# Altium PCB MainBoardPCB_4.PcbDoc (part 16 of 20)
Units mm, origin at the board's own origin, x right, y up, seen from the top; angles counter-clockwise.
Board outline 333.63 x 349.38 mm, 16 copper layers (L1, L2 (GND), L3 (Sign), L4 (GND), L5 (Sign), L6 (PWR/GND), L7(PWR/GND), L8 (Plane_GND), L9 (PWR/GND), L10 (PWR/GND), L11 (PWR/GND), L12 (Sign), L13 (GND), L14 (Sign), L15 (GND), L16), stack 2.502 mm thick; 2205 components, 1648 nets, 8314 pads, 3172 vias.
Unrouted connection lines stored in the file: 5141.
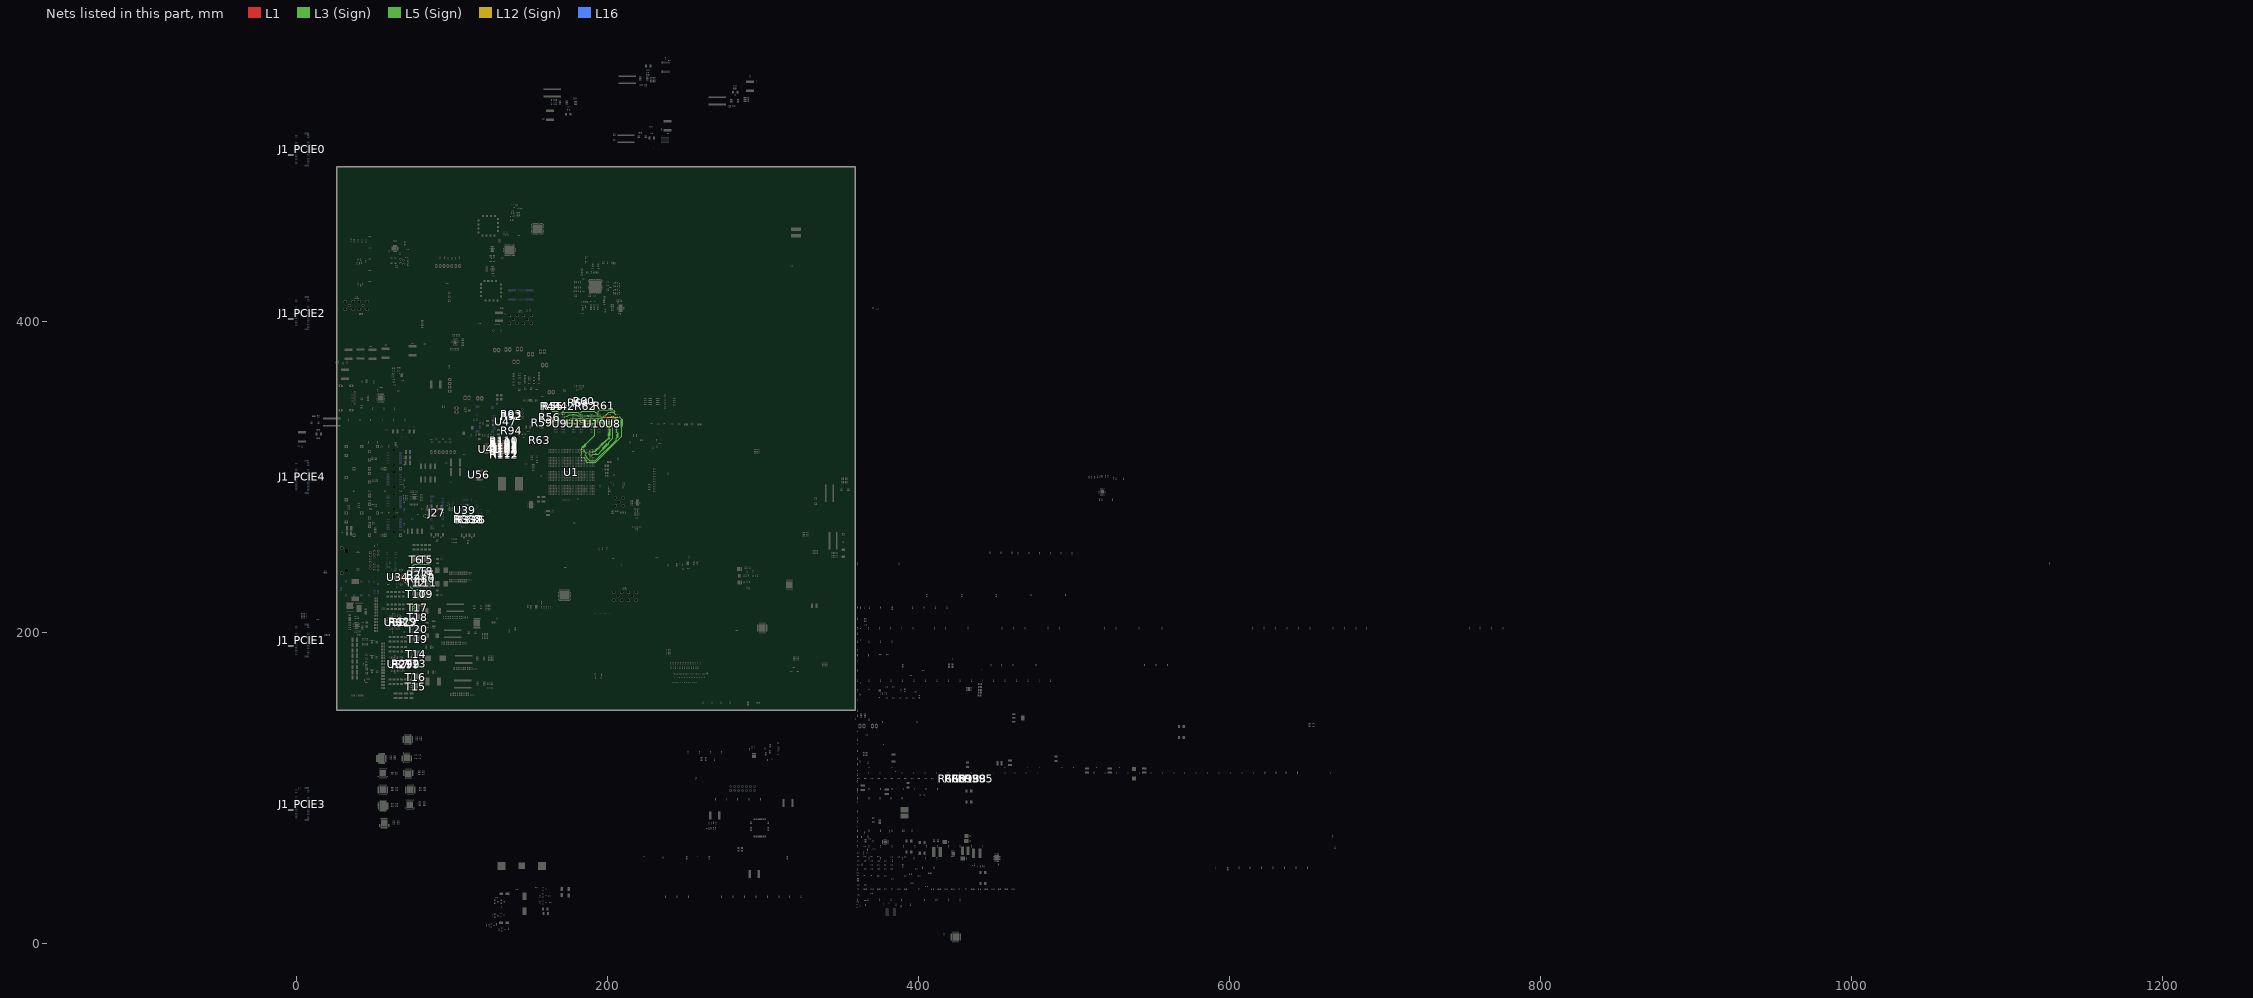
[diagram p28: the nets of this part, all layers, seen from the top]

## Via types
v1: diameter 0.5, hole 0.2, L1 to L16, tented both sides, 1153 vias
v2: diameter 0.5/0.35/0.35/0.35/0.35/0.35/0.35/0.35/0.35/0.35/0.35/0.35/0.35/0.35/0.35/0.5 (per signal layer), hole 0.2, L1 to L16, tented both sides, 548 vias
v3: diameter 0.5, hole 0.2, L1 to L16, 522 vias
v4: diameter 0.5/0.35/0.35/0.35/0.35/0.35/0.35/0.35/0.35/0.35/0.35/0.35/0.35/0.35/0.35/0.5 (per signal layer), hole 0.15, L1 to L16, tented both sides, 266 vias
v5: diameter 0.8, hole 0.4, L1 to L16, tented both sides, 164 vias
v6: diameter 0.35/0/0.35 (per signal layer), hole 0.127, L1 to L3 (Sign), tented both sides, 132 vias
v7: diameter 2.54, hole 1.02, L1 to L16, 125 vias
v8: diameter 1.4, hole 0.5, L1 to L16, tented both sides, 80 vias
v9: diameter 0.35, hole 0.127, L1 to L2 (GND), tented both sides, 36 vias
v10: diameter 0.4, hole 0.2, L1 to L16, 16 vias
v11: diameter 0.25, hole 0.2, L1 to L16, 16 vias
v12: diameter 5, hole 3, L1 to L16, 15 vias
v13: diameter 0.3, hole 0.2, L1 to L16, 15 vias
v14: diameter 0.45, hole 0.15, L1 to L16, 12 vias
v15: diameter 0.5/0.35/0.35/0.35/0.35/0.35/0.35/0.35/0.35/0.35/0.35/0.35/0.35/0.35/0.35/0.45 (per signal layer), hole 0.15, L1 to L16, tented both sides, 10 vias
v16: diameter 0.2/0/0.2 (per signal layer), hole 0.1, L1 to L3 (Sign), tented both sides, 9 vias
v17: diameter 0.4, hole 0.1, L1 to L16, 7 vias
v18: diameter 0.5, hole 0.2, L3 (Sign) to L6 (PWR/GND), tented both sides, 6 vias
v19: diameter 1.65, hole 1.65, L1 to L16, 6 vias
v20: diameter 1.15, hole 1.15, L1 to L16, 6 vias
v21: diameter 0.35/0/0.35 (per signal layer), hole 0.127, L14 (Sign) to L16, tented both sides, 5 vias
v22: diameter 0.2, hole 0.1, L1 to L16, 4 vias
v23: diameter 0.4, hole 0.2, L1 to L16, tented both sides, 2 vias
v24: diameter 0.4, hole 0.15, L1 to L16, 2 vias
v25: diameter 0.508, hole 0.127, L1 to L2 (GND), 2 vias
v26: diameter 0.508, hole 0.127, L2 (GND) to L3 (Sign), 2 vias
v27: diameter 0.5/0.35/0.35/0.35/0.35/0.35/0.35/0.35/0.35/0.35/0.35/0.35/0.35/0.35/0.35/0.5 (per signal layer), hole 0.15, L1 to L16, 2 vias
v28: diameter 0.35, hole 0.127, L3 (Sign) to L6 (PWR/GND), tented both sides, 2 vias
v29: diameter 5.5, hole 3.5, L1 to L16, 1 vias
v30: diameter 0.5/0.35/0.35/0.35/0.35/0.35/0.35/0.35/0.35/0.35/0.35/0.35/0.35/0.35/0.35/0.5 (per signal layer), hole 0.2, L1 to L16, 1 vias
v31: diameter 0.35/0.35/0.35 (per signal layer), hole 0.127, L1 to L3 (Sign), tented both sides, 1 vias
v32: diameter 0.45/0/0.45 (per signal layer), hole 0.15, L1 to L3 (Sign), tented both sides, 1 vias
v33: diameter 0.45/0/0.45 (per signal layer), hole 0.2, L14 (Sign) to L16, tented both sides, 1 vias
v34: diameter 0.35, hole 0.127, L2 (GND) to L3 (Sign), 1 vias
v35: diameter 0.35, hole 0.127, L1 to L2 (GND), 1 vias

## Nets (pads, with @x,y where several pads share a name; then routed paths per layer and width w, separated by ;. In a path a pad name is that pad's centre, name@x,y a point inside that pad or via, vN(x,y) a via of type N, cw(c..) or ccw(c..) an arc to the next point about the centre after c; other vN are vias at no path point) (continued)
DDR4_DQS_ODT0: R44.1 U1.AB30 U8.K3 U9.K3 U10.K3 U11.K3 | length 107.6
  L1 w0.116: v4(170.472,334.857) U9.K3@170.876,335.26 ; v4(181.933,334.857) U11.K3@182.336,335.26 ; U1.AB30@183.397,317.539 v6(183.884,317.052) ; v4(193.393,334.857) U10.K3@193.797,335.26 ; U8.K3@205.257,335.26 v4(205.661,334.857)
  L1 w0.155: v1(163.977,343.555) R44.1@163.977,344.8
  L1 w0.25: v4(188.593,333.264) 188.997,332.86
  L5 (Sign) w0.092: 167.944,341.085 167.944,341.002 168.602,340.344 168.602,336.427 170.172,334.857 v4(170.472,334.857) 170.709,334.857 171.12,335.267 173.139,335.267 173.954,334.453 174.088,334.453 cw(c174.088,334.363) 174.178,334.363 174.178,334.334 ccw(c174.267,334.334) 174.267,334.245 174.536,334.245 ccw(c174.536,334.334) 174.626,334.334 174.626,334.363 cw(c174.715,334.363) 174.715,334.453 176.441,334.453 178.208,334.453 178.601,334.06 180.755,334.06 181.551,334.857 v4(181.933,334.857) 182.566,334.857 182.977,335.267 183.747,335.267 183.972,335.043 183.972,334.696 184.172,334.496 184.934,334.496 185.77,333.66 191.687,333.66 192.884,334.857 193.709,334.857 194.12,335.267 195.118,335.267 195.484,334.901 196.186,334.901 196.783,334.304 196.895,334.304 197.03,334.304 ccw(c197.03,334.393) 197.119,334.393 197.119,334.474 cw(c197.209,334.474) 197.209,334.564 197.477,334.564 cw(c197.477,334.474) 197.567,334.474 197.567,334.304 197.567,333.733 ccw(c197.657,333.733) 197.657,333.644 197.925,333.644 ccw(c197.925,333.733) 198.015,333.733 198.015,334.304 198.015,334.475 cw(c198.104,334.475) 198.104,334.565 198.373,334.565 cw(c198.373,334.475) 198.463,334.475 198.463,334.393 ccw(c198.552,334.393) 198.552,334.304 198.91,334.304 cw(c198.98,334.304) 198.98,334.373 199.289,334.373 cw(c199.289,334.304) 199.358,334.304 199.358,333.855 ccw(c199.448,333.855) 199.448,333.765 199.716,333.765 ccw(c199.716,333.855) 199.806,333.855 199.806,334.214 cw(c199.896,334.214) 199.896,334.304 200.29,334.304 201.429,335.442 205.075,335.442 v4(205.661,334.857)
  L5 (Sign) w0.151: v1(163.977,343.555) 163.977,342.74 164.655,342.062 167.145,342.062 167.944,341.263 167.944,341.085
  L3 (Sign) w0.092: v6(183.884,317.052) 184.243,317.411 184.979,317.411 185.205,317.185 185.205,316.482 186.422,315.264 186.422,314.708 186.421,314.706 186.418,314.706 186.066,314.354 185.884,314.354 185.696,314.166 185.696,313.9 186.28,313.315 186.28,312.749 188.799,310.23 192.379,310.23 205.605,323.456 205.605,324.666 206.306,325.367 206.366,325.428 ccw(c206.296,325.498) 206.366,325.568 206.14,325.794 cw(c206.21,325.865) 206.14,325.935 206.28,326.075 cw(c206.351,326.005) 206.421,326.075 206.647,325.849 ccw(c206.717,325.919) 206.787,325.849 206.858,325.919 206.858,326.275 206.858,326.573 ccw(c206.758,326.573) 206.758,326.672 206.306,326.672 cw(c206.306,326.771) 206.207,326.771 206.207,326.97 cw(c206.306,326.97) 206.306,327.069 206.758,327.069 ccw(c206.758,327.168) 206.858,327.168 206.858,327.466 206.858,327.665 206.858,327.863 206.055,328.665 206.055,334.462 v4(205.661,334.857)
DDR4_DQS_ODT1: U1.AC29
DDR4_PARITY: R42.1 U1.AB26 U8.T3 U9.T3 U10.T3 U11.T3 | length 98
  L1 w0.116: v4(170.472,340.464) U9.T3@170.876,340.06 ; v4(181.933,340.464) U11.T3@182.336,340.06 ; v6(182.909,314.027) U1.AB26@183.397,313.539 ; v4(193.393,340.464) U10.T3@193.797,340.06 ; v15(204.853,340.464) U8.T3@205.257,340.06
  L1 w0.155: v6(172.438,343.555) R42.1@172.438,344.799
  L5 (Sign) w0.092: v4(170.472,340.464) 171.401,341.393 171.535,341.393 ccw(c171.535,341.482) 171.625,341.482 171.625,341.494 cw(c171.714,341.494) 171.714,341.584 171.983,341.584 cw(c171.983,341.494) 172.073,341.494 172.073,341.393 172.073,341.291 ccw(c172.162,341.291) 172.162,341.202 172.431,341.202 ccw(c172.431,341.291) 172.52,341.291 172.52,341.303 cw(c172.61,341.303) 172.61,341.393 173.009,341.393 181.004,341.393 v4(181.933,340.464) 183.734,342.265 188.493,342.265 189.683,342.265 cw(c189.683,342.196) 189.752,342.196 189.752,342.188 ccw(c189.821,342.188) 189.821,342.118 190.029,342.118 ccw(c190.029,342.188) 190.098,342.188 190.098,342.196 cw(c190.168,342.196) 190.168,342.265 190.271,342.265 191.592,342.265 v4(193.393,340.464) 193.568,340.639 193.943,340.639 194.285,340.982 194.285,342.24 194.907,342.862 200.863,342.862 202.534,342.862 cw(c202.534,342.772) 202.623,342.772 202.623,342.659 ccw(c202.713,342.659) 202.713,342.57 202.982,342.57 ccw(c202.982,342.659) 203.071,342.659 203.071,342.862 203.071,343.065 cw(c203.161,343.065) 203.161,343.154 203.429,343.154 cw(c203.429,343.065) 203.519,343.065 203.519,342.862 203.519,342.659 ccw(c203.608,342.659) 203.608,342.57 203.877,342.57 ccw(c203.877,342.659) 203.967,342.659 203.967,342.772 cw(c204.056,342.772) 204.056,342.862 204.191,342.862 204.853,342.199 v15(204.853,340.464)
  L3 (Sign) w0.092: v4(170.472,340.464) 171.013,341.005 171.013,341.085 ; v6(182.909,314.027) 183.49,314.607 183.49,316.403 183.179,316.713 183.179,317.344 183.49,317.654 183.49,318.295 183.84,318.646 183.911,318.716 ccw(c183.84,318.786) 183.911,318.857 183.788,318.979 cw(c183.858,319.049) 183.788,319.119 183.929,319.26 cw(c183.999,319.189) 184.069,319.26 184.261,319.067 184.676,318.653 ccw(c184.746,318.723) 184.816,318.653 184.957,318.793 ccw(c184.886,318.863) 184.957,318.933 184.542,319.348 184.35,319.54 cw(c184.42,319.611) 184.35,319.681 184.49,319.821 cw(c184.56,319.751) 184.63,319.821 184.823,319.629 185.201,319.251 ccw(c185.271,319.321) 185.341,319.251 185.481,319.391 ccw(c185.411,319.461) 185.481,319.531 185.104,319.909 184.911,320.102 cw(c184.981,320.172) 184.911,320.242 185.051,320.383 cw(c185.122,320.312) 185.192,320.383 185.384,320.19 185.76,319.814 ccw(c185.83,319.884) 185.9,319.814 186.041,319.955 ccw(c185.971,320.025) 186.041,320.095 185.665,320.471 185.472,320.663 cw(c185.543,320.733) 185.472,320.804 185.613,320.944 cw(c185.683,320.874) 185.753,320.944 185.876,320.822 ccw(c185.946,320.892) 186.016,320.822 186.715,321.521 191.937,326.742 191.937,334.292 192.646,335.002 192.646,336.014 193.206,336.574 196.129,336.574 201.059,341.503 203.814,341.503 v15(204.853,340.464)
  L3 (Sign) w0.151: 171.013,341.085 171.013,341.464 172.428,342.879 172.428,343.545 v6(172.438,343.555)
DDR4_RAM_RST_N: R60.1 U1.AB25 U8.P1 U9.P1 U10.P1 U11.P1 | length 99.4
  L1 w0.116: U9.P1@172.476,338.46 v6(172.879,338.864) ; U1.AB25@183.397,312.539 v6(183.884,313.027) ; U11.P1@183.936,338.46 v6(184.34,338.864) ; U10.P1@195.397,338.46 v4(195.8,338.864) ; U8.P1@206.857,338.46 v4(207.261,338.864)
  L12 (Sign) w0.092: v4(195.8,338.864) 196.374,338.29 201.123,338.29 201.218,338.385 202.425,338.385 202.56,338.385 ccw(c202.56,338.475) 202.649,338.475 202.649,338.652 cw(c202.739,338.652) 202.739,338.742 203.007,338.742 cw(c203.007,338.652) 203.097,338.652 203.097,338.385 203.097,338.118 ccw(c203.187,338.118) 203.187,338.028 203.455,338.028 ccw(c203.455,338.118) 203.545,338.118 203.545,338.385 203.545,338.652 cw(c203.634,338.652) 203.634,338.742 203.903,338.742 cw(c203.903,338.652) 203.993,338.652 203.993,338.475 ccw(c204.082,338.475) 204.082,338.385 204.483,338.385 206.782,338.385 v4(207.261,338.864)
  L3 (Sign) w0.092: v6(172.879,338.864) 174.191,338.864 175.387,340.06 175.672,340.06 cw(c175.672,339.951) 175.782,339.951 175.782,339.92 ccw(c175.892,339.92) 175.892,339.81 176.222,339.81 ccw(c176.222,339.92) 176.332,339.92 176.332,339.951 cw(c176.441,339.951) 176.441,340.06 176.606,340.06 179.992,340.06 180.792,339.26 183.943,339.26 v6(184.34,338.864) 184.736,339.26 185.89,339.26 187.297,339.26 ccw(c187.297,339.35) 187.387,339.35 187.387,339.625 cw(c187.476,339.625) 187.476,339.715 187.745,339.715 cw(c187.745,339.625) 187.834,339.625 187.834,339.26 187.834,339.02 ccw(c187.924,339.02) 187.924,338.93 188.193,338.93 ccw(c188.193,339.02) 188.282,339.02 188.282,339.171 cw(c188.372,339.171) 188.372,339.26 188.506,339.26 195.404,339.26 v4(195.8,338.864) ; v6(183.884,313.027) 184.305,313.027 184.7,312.632 185.055,312.632 185.382,312.306 185.382,311.656 186.28,310.757 186.28,309.749 186.606,309.423 187.731,309.423 192.65,309.423 192.689,309.462 192.697,309.462 209.194,325.959 209.194,331.495 209.194,332.123 ccw(c209.057,332.123) 209.057,332.26 208.801,332.26 cw(c208.801,332.398) 208.663,332.398 208.663,332.672 cw(c208.801,332.672) 208.801,332.81 209.194,332.81 209.71,332.81 ccw(c209.71,332.947) 209.847,332.947 209.847,333.222 ccw(c209.71,333.222) 209.71,333.359 209.194,333.359 208.801,333.359 cw(c208.801,333.496) 208.663,333.496 208.663,333.771 cw(c208.801,333.771) 208.801,333.908 209.194,333.908 209.71,333.908 ccw(c209.71,334.046) 209.847,334.046 209.847,334.32 ccw(c209.71,334.32) 209.71,334.458 209.194,334.458 208.801,334.458 cw(c208.801,334.595) 208.663,334.595 208.663,334.87 cw(c208.801,334.87) 208.801,335.007 209.194,335.007 209.71,335.007 ccw(c209.71,335.145) 209.847,335.145 209.847,335.419 ccw(c209.71,335.419) 209.71,335.557 209.194,335.557 208.801,335.557 cw(c208.801,335.694) 208.663,335.694 208.663,335.969 cw(c208.801,335.969) 208.801,336.106 209.194,336.106 209.71,336.106 ccw(c209.71,336.243) 209.847,336.243 209.847,336.518 ccw(c209.71,336.518) 209.71,336.655 209.332,336.655 cw(c209.332,336.793) 209.194,336.793 209.194,336.93 v4(207.261,338.864)
DDR4_RAS: R59.1 U1.AH27 U8.L5 U9.L5 U10.L5 U11.L5 | length 99.3
  L1 w0.116: U9.L5@166.876,336.06 167.272,336.457 v4(167.275,336.457) ; U11.L5@178.336,336.06 178.733,336.457 v4(178.735,336.457) ; U1.AH27@189.397,314.539 v6(189.884,315.027) ; U10.L5@189.797,336.06 190.193,336.457 v4(190.195,336.457) ; U8.L5@201.257,336.06 201.653,336.457 v3(201.656,336.457)
  L1 w0.155: R59.1@158.737,334.7 v1(159.982,334.7)
  L12 (Sign) w0.092: 165.251,335.813 166.114,335.813 166.758,336.457 v4(167.275,336.457) 167.537,336.457 167.858,336.778 168.277,336.778 168.566,336.488 168.79,336.488 169.149,336.488 cw(c169.149,336.398) 169.238,336.398 169.238,336.342 ccw(c169.328,336.342) 169.328,336.252 169.596,336.252 ccw(c169.596,336.342) 169.686,336.342 169.686,336.398 cw(c169.775,336.398) 169.775,336.488 170.044,336.488 cw(c170.044,336.398) 170.134,336.398 170.134,336.342 ccw(c170.223,336.342) 170.223,336.252 170.492,336.252 ccw(c170.492,336.342) 170.582,336.342 170.582,336.398 cw(c170.671,336.398) 170.671,336.488 170.715,336.488 172.923,336.488 173.147,336.488 173.505,336.488 cw(c173.505,336.398) 173.595,336.398 173.595,336.3 ccw(c173.684,336.3) 173.684,336.211 173.953,336.211 ccw(c173.953,336.3) 174.043,336.3 174.043,336.398 cw(c174.132,336.398) 174.132,336.488 175.628,336.488 175.659,336.457 v4(178.735,336.457) 178.977,336.457 179.349,336.829 180.162,336.829 180.705,336.287 184.769,336.287 184.996,336.06 185.807,336.06 185.91,336.06 ccw(c185.91,336.13) 185.98,336.13 185.98,336.293 cw(c186.049,336.293) 186.049,336.362 186.257,336.362 cw(c186.257,336.293) 186.326,336.293 186.326,336.06 186.326,335.828 ccw(c186.395,335.828) 186.395,335.758 186.603,335.758 ccw(c186.603,335.828) 186.672,335.828 186.672,335.991 cw(c186.741,335.991) 186.741,336.06 186.868,336.06 189.282,336.06 189.679,336.457 v4(190.195,336.457) 190.458,336.457 190.779,336.778 191.197,336.778 191.487,336.488 192.022,335.953 197.764,335.953 198.156,335.953 ccw(c198.156,336.043) 198.245,336.043 198.245,336.152 cw(c198.335,336.152) 198.335,336.241 198.603,336.241 cw(c198.603,336.152) 198.693,336.152 198.693,335.953 198.693,335.754 ccw(c198.782,335.754) 198.782,335.665 199.051,335.665 ccw(c199.051,335.754) 199.141,335.754 199.141,335.864 cw(c199.23,335.864) 199.23,335.953 199.365,335.953 199.502,335.953 ccw(c199.502,336.043) 199.592,336.043 199.592,336.152 cw(c199.681,336.152) 199.681,336.241 199.95,336.241 cw(c199.95,336.152) 200.04,336.152 200.04,335.953 200.04,335.864 ccw(c200.129,335.864) 200.129,335.774 200.398,335.774 ccw(c200.398,335.864) 200.487,335.864 cw(c200.577,335.864) 200.577,335.953 200.711,335.953 201.215,336.457 v3(201.656,336.457)
  L12 (Sign) w0.151: v1(159.982,334.7) 163.09,334.7 164.203,335.813 165.251,335.813
  L3 (Sign) w0.092: v6(189.884,315.027) 190.232,315.374 190.232,316.074 190.672,316.514 190.938,316.514 192.232,316.514 192.381,316.663 192.469,316.751 ccw(c192.381,316.839) 192.469,316.928 192.438,316.959 cw(c192.526,317.047) 192.438,317.135 192.614,317.311 cw(c192.702,317.223) 192.79,317.311 192.91,317.192 192.931,317.17 ccw(c193.019,317.259) 193.107,317.17 193.284,317.347 ccw(c193.196,317.435) 193.284,317.523 193.262,317.544 193.143,317.664 cw(c193.231,317.752) 193.143,317.84 193.319,318.017 cw(c193.407,317.928) 193.495,318.017 193.615,317.897 193.639,317.873 ccw(c193.727,317.961) 193.815,317.873 193.992,318.049 ccw(c193.903,318.137) 193.992,318.225 193.967,318.25 193.848,318.369 cw(c193.936,318.457) 193.848,318.545 194.024,318.722 cw(c194.112,318.634) 194.2,318.722 194.32,318.602 194.473,318.449 ccw(c194.562,318.537) 194.65,318.449 194.826,318.625 ccw(c194.738,318.713) 194.826,318.801 194.673,318.955 194.553,319.074 cw(c194.641,319.162) 194.553,319.251 194.729,319.427 cw(c194.817,319.339) 194.906,319.427 195.025,319.307 195.098,319.235 ccw(c195.186,319.323) 195.274,319.235 195.45,319.411 ccw(c195.362,319.499) 195.45,319.587 195.378,319.66 195.258,319.779 cw(c195.346,319.868) 195.258,319.956 195.434,320.132 cw(c195.523,320.044) 195.611,320.132 195.73,320.012 195.826,319.917 ccw(c195.914,320.005) 196.002,319.917 196.179,320.093 ccw(c196.09,320.181) 196.179,320.269 196.083,320.365 195.963,320.485 cw(c196.051,320.573) 195.963,320.661 196.14,320.837 cw(c196.228,320.749) 196.316,320.837 196.435,320.718 196.589,320.564 ccw(c196.677,320.652) 196.765,320.564 196.941,320.74 ccw(c196.853,320.829) 196.941,320.917 196.788,321.07 196.668,321.19 cw(c196.757,321.278) 196.668,321.366 196.845,321.542 cw(c196.933,321.454) 197.021,321.542 197.14,321.423 197.232,321.331 ccw(c197.32,321.419) 197.408,321.331 197.585,321.508 ccw(c197.496,321.596) 197.585,321.684 197.493,321.775 197.373,321.895 cw(c197.462,321.983) 197.373,322.071 197.55,322.247 cw(c197.638,322.159) 197.726,322.247 197.846,322.128 197.961,322.013 ccw(c198.049,322.101) 198.137,322.013 198.313,322.189 ccw(c198.225,322.277) 198.313,322.365 198.198,322.48 198.079,322.6 cw(c198.167,322.688) 198.079,322.776 198.255,322.953 cw(c198.343,322.864) 198.431,322.953 198.551,322.833 198.702,322.682 ccw(c198.79,322.77) 198.878,322.682 199.054,322.858 ccw(c198.966,322.946) 199.054,323.035 198.903,323.186 198.784,323.305 cw(c198.872,323.393) 198.784,323.481 198.96,323.658 cw(c199.048,323.569) 199.136,323.658 199.256,323.538 199.341,323.453 ccw(c199.43,323.541) 199.518,323.453 199.694,323.629 ccw(c199.606,323.717) 199.694,323.805 199.697,323.802 cw(c199.785,323.891) 199.697,323.979 199.873,324.155 cw(c199.961,324.067) 200.049,324.155 200.201,324.003 ccw(c200.289,324.091) 200.377,324.003 200.554,324.179 ccw(c200.466,324.267) 200.554,324.356 200.402,324.508 cw(c200.49,324.596) 200.402,324.684 200.578,324.86 cw(c200.666,324.772) 200.754,324.86 201.149,324.465 ccw(c201.237,324.554) 201.325,324.465 201.502,324.642 ccw(c201.413,324.73) 201.502,324.818 201.107,325.213 cw(c201.195,325.301) 201.107,325.389 201.224,325.507 201.224,325.653 201.224,326.255 ccw(c201.1,326.255) 201.1,326.38 200.859,326.38 cw(c200.859,326.505) 200.734,326.505 200.734,326.754 cw(c200.859,326.754) 200.859,326.879 201.224,326.879 201.708,326.879 ccw(c201.708,327.003) 201.833,327.003 201.833,327.253 ccw(c201.708,327.253) 201.708,327.377 201.224,327.377 200.859,327.377 cw(c200.859,327.502) 200.734,327.502 200.734,327.751 cw(c200.859,327.751) 200.859,327.876 201.224,327.876 201.708,327.876 ccw(c201.708,328) 201.833,328 201.833,328.25 ccw(c201.708,328.25) 201.708,328.374 201.349,328.374 cw(c201.349,328.499) 201.224,328.499 201.224,328.748 cw(c201.349,328.748) 201.349,328.873 201.708,328.873 ccw(c201.708,328.998) 201.833,328.998 201.833,329.247 ccw(c201.708,329.247) 201.708,329.372 201.224,329.372 cw(c201.224,329.478) 201.118,329.478 201.118,329.764 cw(c201.224,329.764) 201.224,329.87 201.708,329.87 ccw(c201.708,329.995) 201.833,329.995 201.833,330.244 ccw(c201.708,330.244) 201.708,330.369 201.224,330.369 201.133,330.369 cw(c201.133,330.493) 201.009,330.493 201.009,330.743 cw(c201.133,330.743) 201.133,330.867 201.224,330.867 ccw(c201.224,330.931) 201.288,330.931 201.288,331.303 ccw(c201.224,331.303) 201.224,331.366 201.223,331.366 cw(c201.223,331.491) 201.098,331.491 201.098,331.74 cw(c201.223,331.74) 201.223,331.865 201.224,331.865 ccw(c201.224,331.969) 201.329,331.969 201.329,332.259 ccw(c201.224,332.259) 201.224,332.363 cw(c201.224,332.484) 201.103,332.484 201.103,332.741 cw(c201.224,332.741) 201.224,332.862 201.708,332.862 ccw(c201.708,332.986) 201.833,332.986 201.833,333.236 ccw(c201.708,333.236) 201.708,333.36 201.224,333.36 cw(c201.224,333.485) 201.1,333.485 201.1,333.734 cw(c201.224,333.734) 201.224,333.859 201.708,333.859 ccw(c201.708,333.984) 201.833,333.984 201.833,334.233 ccw(c201.708,334.233) 201.708,334.358 201.349,334.358 cw(c201.349,334.482) 201.224,334.482 201.224,334.607 201.224,335.03 201.371,335.177 201.371,335.877 201.656,336.162 v3(201.656,336.457)
  other v19: 2.275,99.582
DDR4_TEN: R56.1 U8.N6 U9.N6 U10.N6 U11.N6 | length 42.1
  L1 w0.112: 165.251,338.056 v6(165.665,338.056)
  L1 w0.116: v6(165.665,338.056) U9.N6@166.068,337.653 ; v6(177.125,338.056) U11.N6@177.529,337.653 ; v6(188.586,338.056) U10.N6@188.989,337.653 ; v6(197.878,339.319) 199.536,337.66 U8.N6@200.457,337.66
  L1 w0.155: R56.1@163.36,338.184 164.159,338.184 164.287,338.056 165.251,338.056
  L3 (Sign) w0.092: v6(165.665,338.056) 166.061,337.66 168.338,337.66 169.439,336.56 175.628,336.56 176.729,337.66
  L3 (Sign) w0.116: 176.729,337.66 v6(177.125,338.056) 177.521,337.66 183.136,337.66 183.143,337.668 188.197,337.668 v6(188.586,338.056) 188.982,337.66 190.855,337.66 190.869,337.674 191.154,337.674 191.313,337.833 192.222,337.833 192.387,337.668 196.227,337.668 v6(197.878,339.319)
DDR4_WE: R55.1 U1.AG29 U8.L2 U9.L2 U10.L2 U11.L2 | length 108.5
  L1 w0.116: U9.L2@171.676,336.06 v4(172.079,335.657) ; U11.L2@183.136,336.06 v4(183.54,335.657) ; U1.AG29@188.397,316.539 188.811,316.125 v6(188.811,316.088) ; U10.L2@194.597,336.06 v4(195,335.657) ; v4(205.653,336.464) U8.L2@206.057,336.06
  L1 w0.155: v1(165.186,343.555) R55.1@165.186,344.8
  L5 (Sign) w0.092: 168.291,341.085 168.291,341.007 168.793,340.505 168.793,336.675 170.132,335.336 170.605,335.336 170.62,335.351 170.791,335.351 171.097,335.657 171.317,335.657 v4(172.079,335.657) 172.129,335.706 173.291,335.706 174.157,334.84 174.291,334.84 ccw(c174.291,334.93) 174.38,334.93 174.38,334.97 cw(c174.47,334.97) 174.47,335.06 174.739,335.06 cw(c174.739,334.97) 174.828,334.97 174.828,334.93 ccw(c174.918,334.93) 174.918,334.84 176.289,334.84 178.225,334.84 178.587,334.478 180.897,334.478 181.669,335.25 182.326,335.25 182.733,335.657 ; v4(205.653,336.464) 205.316,336.464 204.486,335.634 204.352,335.634 cw(c204.352,335.724) 204.262,335.724 204.262,335.829 ccw(c204.173,335.829) 204.173,335.919 203.904,335.919 ccw(c203.904,335.829) 203.814,335.829 203.814,335.724 cw(c203.725,335.724) 203.725,335.634 203.456,335.634 cw(c203.456,335.724) 203.367,335.724 203.367,335.75 ccw(c203.277,335.75) 203.277,335.839 203.008,335.839 ccw(c203.008,335.75) 202.919,335.75 202.919,335.724 cw(c202.829,335.724) 202.829,335.634 202.552,335.634 201.349,335.634 200.925,335.21 200.79,335.21 ccw(c200.79,335.12) 200.701,335.12 200.701,335.023 cw(c200.611,335.023) 200.611,334.933 200.342,334.933 cw(c200.342,335.023) 200.253,335.023 200.253,335.21 200.253,335.257 ccw(c200.163,335.257) 200.163,335.347 199.895,335.347 ccw(c199.895,335.257) 199.805,335.257 199.805,335.21 199.805,334.893 cw(c199.715,334.893) 199.715,334.803 199.447,334.803 cw(c199.447,334.893) 199.357,334.893 199.357,335.21 199.357,335.257 ccw(c199.268,335.257) 199.268,335.347 198.999,335.347 ccw(c198.999,335.257) 198.909,335.257 cw(c198.862,335.257) 198.862,335.21 198.509,335.21 cw(c198.509,335.257) 198.462,335.257 ccw(c198.372,335.257) 198.372,335.347 198.103,335.347 ccw(c198.103,335.257) 198.014,335.257 198.014,335.209 198.014,334.893 cw(c197.924,334.893) 197.924,334.803 197.656,334.803 cw(c197.656,334.893) 197.566,334.893 197.566,335.209 197.566,335.526 ccw(c197.476,335.526) 197.476,335.616 197.208,335.616 ccw(c197.208,335.526) 197.118,335.526 197.118,335.209 197.118,334.893 cw(c197.029,334.893) 197.029,334.803 196.76,334.803 cw(c196.76,334.893) 196.67,334.893 196.67,335.209 196.67,335.526 ccw(c196.581,335.526) 196.581,335.616 196.312,335.616 ccw(c196.312,335.526) 196.223,335.526 196.223,335.299 cw(c196.133,335.299) 196.133,335.209 195.783,335.209 195.721,335.209 195.274,335.657 v4(195,335.657) 194.193,335.657 193.797,335.26 192.558,335.26 191.777,334.48 188.561,334.48 188.457,334.48 ccw(c188.457,334.411) 188.387,334.411 cw(c188.318,334.411) 188.318,334.341 188.111,334.341 cw(c188.111,334.411) 188.041,334.411 188.041,334.48 188.041,334.707 ccw(c187.972,334.707) 187.972,334.776 187.764,334.776 ccw(c187.764,334.707) 187.695,334.707 187.695,334.549 cw(c187.626,334.549) 187.626,334.48 186.969,334.48 185.344,334.48 184.556,335.267 184.187,335.267 183.798,335.657 v4(183.54,335.657) ; 182.733,335.657 v4(183.54,335.657) ; 182.733,335.657 v4(183.54,335.657)
  L5 (Sign) w0.151: v1(165.186,343.555) 165.186,342.893 165.535,342.544 167.348,342.544 168.291,341.601 168.291,341.085
  L3 (Sign) w0.092: v6(188.811,316.088) 188.92,316.088 188.563,315.731 188.563,315.57 188.335,315.341 188.335,314.327 188.397,314.264 188.397,314.06 188.826,313.631 190.119,313.631 190.33,313.842 190.33,314.212 190.592,314.473 191.534,314.473 191.651,314.59 191.872,314.59 191.971,314.59 ccw(c191.971,314.689) 192.07,314.689 cw(c192.169,314.689) 192.169,314.788 192.368,314.788 cw(c192.368,314.689) 192.467,314.689 192.467,314.59 ccw(c192.566,314.59) 192.566,314.491 192.765,314.491 ccw(c192.765,314.59) 192.864,314.59 192.864,314.697 cw(c192.963,314.697) 192.963,314.796 193.162,314.796 cw(c193.162,314.697) 193.261,314.697 193.261,314.689 ccw(c193.36,314.689) 193.36,314.59 193.789,314.59 194.01,314.59 ; 194.009,314.591 196.884,317.466 196.995,317.576 cw(c197.065,317.506) 197.135,317.576 197.133,317.579 ; 197.132,317.579 ccw(c197.203,317.649) 197.273,317.579 197.413,317.719 ccw(c197.343,317.79) 197.413,317.86 197.345,317.927 196.991,318.281 cw(c197.062,318.352) 196.991,318.422 197.132,318.562 cw(c197.202,318.492) 197.272,318.562 197.626,318.208 197.694,318.14 ccw(c197.764,318.211) 197.834,318.14 197.975,318.281 ccw(c197.904,318.351) 197.975,318.421 197.907,318.489 197.553,318.843 cw(c197.623,318.913) 197.553,318.983 197.693,319.124 cw(c197.763,319.053) 197.834,319.124 198.188,318.77 198.255,318.702 ccw(c198.325,318.772) 198.396,318.702 198.536,318.842 ccw(c198.466,318.912) 198.536,318.983 198.468,319.05 198.114,319.404 cw(c198.184,319.475) 198.114,319.545 198.255,319.685 cw(c198.325,319.615) 198.395,319.685 198.749,319.331 198.817,319.263 ccw(c198.887,319.333) 198.957,319.263 199.097,319.404 ccw(c199.027,319.474) 199.097,319.544 199.03,319.612 198.676,319.966 cw(c198.746,320.036) 198.676,320.106 198.816,320.247 cw(c198.886,320.176) 198.956,320.247 199.311,319.892 199.376,319.827 ccw(c199.446,319.897) 199.516,319.827 199.656,319.968 ccw(c199.586,320.038) 199.656,320.108 199.591,320.173 199.237,320.527 cw(c199.307,320.597) 199.237,320.668 199.377,320.808 cw(c199.448,320.738) 199.518,320.808 199.872,320.454 199.937,320.389 ccw(c200.007,320.459) 200.078,320.389 200.218,320.529 ccw(c200.148,320.599) 200.218,320.669 200.153,320.735 199.799,321.089 cw(c199.869,321.159) 199.799,321.229 199.939,321.369 cw(c200.009,321.299) 200.079,321.369 200.433,321.015 200.504,320.945 ccw(c200.574,321.015) 200.644,320.945 200.784,321.085 ccw(c200.714,321.156) 200.784,321.226 cw(c200.855,321.296) 200.784,321.366 200.855,321.436 200.855,322.107 203.626,324.879 203.626,335.895 203.898,336.168 203.898,336.931 203.91,336.942 203.91,336.947 204.419,337.456 204.423,337.456 204.635,337.668 205.034,337.668 205.263,337.439 205.263,336.855 v4(205.653,336.464)
DDR4_ZQ: U1.AB23
DDR4_ZQ_1: R61.1 U8.F6 | length 2.2
  L1 w0.254: v1(198.343,331.916) 198.475,332.048 200.445,332.048 U8.F6@200.457,332.06
DDR4_ZQ_2: R62.1 U10.F6 | length 0.6
  L1 w0.25: v4(188.593,332.464) U10.F6@188.997,332.06
DDR4_ZQ_3: R63.1 U9.F6
DDR4_ZQ_4: R64.1 U11.F6
DEVSLP: J27.38
DEVSLP_PCIE0: J1_PCIE0.40 R395.1 U1.AE5
  other v2: 186.397,292.539
DEVSLP_PCIE1: J1_PCIE1.40 R398.1 U1.AD4
  other v2: 185.397,291.539
DEVSLP_PCIE2: J1_PCIE2.40 R618.1 U1.AE4
  other v2: 186.397,291.539
DEVSLP_PCIE3: J1_PCIE3.40 R659.1 U1.AB4
  other v2: 183.397,291.539
DEVSLP_PCIE4: J1_PCIE4.40 R660.1 U1.AC4
  other v2: 184.397,291.539
DH1: T5.4 T6.4 U34.23 | length 21.5
  L1 w0.254: U34.23@67.322,236.639 67.949,236.639 69.436,238.125 v6(70.117,238.125) ; T5.4@85.882,243.723 v6(85.882,243.755)
  L3 (Sign) w0.254: v6(70.117,238.125) 75.714,243.723 v6(78.882,243.723) 78.914,243.755 v6(85.882,243.755)
DH1_1: T13.4 U37.23 | length 1.1
  L1 w0.5: T13.4@80.042,181.813 v1(81.129,181.813)
DH1_2: T17.4 U38.23 | length 13.5
  L1 w0.254: U38.23@65.953,207.714 67.479,207.714 v6(67.796,208.031) ; v6(80.18,217.889) T17.4@80.998,217.889
  L3 (Sign) w0.254: v6(67.796,208.031) 67.796,210.036 ; 74.923,213.696 74.923,216.666 75.567,217.31 79.083,217.31 79.662,217.889 v6(80.18,217.889)
DH2: T9.4 T10.4 U34.18 | length 17.5
  L1 w0.254: U34.18@67.322,234.139 67.324,234.137 68.428,234.137 v6(69.863,232.702) ; v6(82.067,227.505) T9.4@82.072,227.501
  L3 (Sign) w0.254: v6(69.863,232.702) 75.064,227.501 v6(75.078,227.501) 75.082,227.505 v6(82.067,227.505)
DH2_1: T15.4 U37.18 | length 1.1
  L1 w0.5: T15.4@79.789,167.011 v1(80.876,167.011)
DH2_2: T19.4 U38.18 | length 1.9
  L1 w0.254: U38.18@65.953,205.214 67.536,205.214 67.744,205.006
DIR_CMD: R92.2 U47.A2 | length 4.9
  L16 w0.098: U47.A2@135.129,336.204 135.127,337.538 136.651,339.062 R92.2@138.087,339.062
DIR_DAT0_H: R93.2 U47.A3 | length 5.9
  L16 w0.098: U47.A3@134.727,336.204 134.727,337.729 137.102,340.103 R93.2@138.087,340.103
DIR_DAT1_H: R94.2 U47.E3
DL1: R275.2 T7.4 T8.4 U34.21 | length 19.6
  L1 w0.254: U34.21@67.322,235.639 70.805,235.639 v6(71.387,236.22) ; v6(85.869,236.489) T8.4@85.882,236.489
  L3 (Sign) w0.254: v6(71.387,236.22) 71.655,236.489 v6(78.867,236.489) 79.613,236.489 v6(80.488,237.364) 81.363,236.489 v6(85.869,236.489)
DL1_1: R292.2 T14.4 U37.21 | length 3.6
  L1 w0.254: U37.21@67.675,179.817 68.726,179.817 68.825,179.915 R292.2@70.161,179.915
  L1 w0.5: v1(73.127,184.15) T14.4@74.214,184.15
DL1_2: R629.2 T18.4 U38.21 | length 9.9
  L1 w0.254: U38.21@65.953,206.714 66.916,206.714 67.166,206.964 R629.2@68.206,206.964 ; v6(73.85,207.802) 73.855,207.797 T18.4@75.173,207.797
  L3 (Sign) w0.254: v6(67.43,206.951) 69.233,208.755 ; 71.23,205.181 v6(73.85,207.802)
DL2: R280.2 T11.4 T12.4 U34.20 | length 15.8
  L1 w0.254: U34.20@67.322,235.139 69.941,235.139 v6(70.129,234.95)
  L3 (Sign) w0.254: v6(70.129,234.95) 70.316,234.764 v6(75.072,234.764) v6(82.072,234.764) ; v6(80.488,233.889) 80.488,234.764
DL2_1: R299.2 T16.4 U37.20 | length 3.7
  L1 w0.254: U37.20@67.675,179.317 69.396,179.317 69.646,179.067 R299.2@70.211,179.067
  L1 w0.5: v1(72.923,169.38) T16.4@74.01,169.38
DL2_2: R317.2 T20.4 U38.20 | length 2.3
  L1 w0.254: U38.20@65.953,206.214 66.991,206.214 67.166,206.039 68.212,206.039 R317.2@68.206,206.039
DS_TCK: U39.20 U56.12
DS_TDI: R336.2 U39.23 U56.14
DS_TDO: R337.2 U39.21 U56.11
DS_TMS: R338.2 U39.22 U56.13
eMMC_clk: R112.2 U41.M6 | length 13.8
  L1 w0.098: v6(131.416,314.211) 133.103,314.211 R112.2@133.116,314.223
  L3 (Sign) w0.098: v16(121.938,318.591) 122.886,319.54 125.022,319.54 130.352,314.211 v6(131.416,314.211)
eMMC_cmd: R111.2 U41.M5 | length 13.3
  L1 w0.098: v6(131.407,315.214) R111.2@133.116,315.214
  L3 (Sign) w0.098: v16(121.938,319.091) 122.157,319.091 122.804,319.738 125.104,319.738 129.629,315.214 v6(131.407,315.214)
eMMC_data0: R105.2 U41.A3 | length 6.2
  L1 w0.098: v6(131.407,321.335) R105.2@133.116,321.335
  L3 (Sign) w0.098: v16(127.438,320.091) 128.682,321.335 v6(131.407,321.335)
eMMC_data1: R107.2 U41.A4 | length 5.8
  L1 w0.098: U41.A4@127.438,319.591 130.833,319.591 131.121,319.303 R107.2@133.116,319.303
eMMC_data2: R108.2 U41.A5 | length 6.4
  L1 w0.098: U41.A5@127.438,319.091 128.558,319.091 130.378,317.271 R108.2@133.116,317.271
eMMC_data3: R110.2 U41.B2 | length 7.3
  L1 w0.098: v32(131.416,323.367) R110.2@133.116,323.367
  L3 (Sign) w0.098: v16(126.938,320.591) 129.714,323.367 v32(131.416,323.367)
eMMC_data4: R101.2 U41.B3 | length 7.1
  L1 w0.098: v16(126.929,320.091) U41.B3@126.938,320.091 ; v6(131.407,322.351) R101.2@133.116,322.351
  L3 (Sign) w0.098: v16(126.929,320.091) 128.897,322.059 128.905,322.059 129.197,322.351 v6(131.407,322.351)
eMMC_data5: R102.2 U41.B4 | length 6.6
  L1 w0.098: v6(131.407,320.319) 131.466,320.319 131.665,320.518 132.917,320.518 R102.2@133.116,320.319
  L3 (Sign) w0.098: v16(126.938,319.591) 127.478,319.591 128.207,320.319 v6(131.407,320.319)
eMMC_data6: R103.2 U41.B5 | length 6.5
  L1 w0.098: v6(131.407,318.287) R103.2@133.116,318.287
  L3 (Sign) w0.098: v16(126.938,319.091) 130.427,319.091 131.231,318.287 v6(131.407,318.287)
eMMC_data7: R104.2 U41.B6 | length 7.1
  L1 w0.098: v6(131.416,316.255) R104.2@133.116,316.255
  L3 (Sign) w0.098: v16(126.938,318.591) 128.563,318.591 130.899,316.255 v6(131.416,316.255)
